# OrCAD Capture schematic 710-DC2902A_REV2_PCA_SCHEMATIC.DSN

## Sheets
1 PAGE2
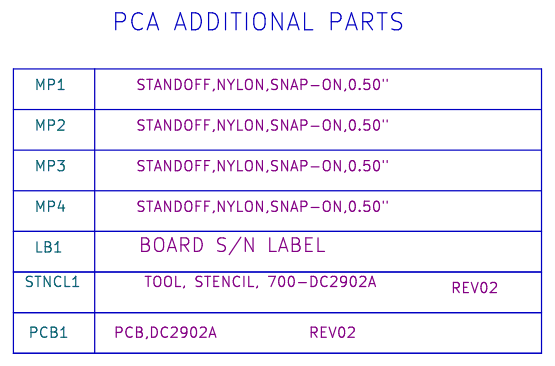
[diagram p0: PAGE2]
2 PAGE1: size C; note: ULTRA TINY 1.5A TEC uMODULE REGULATOR
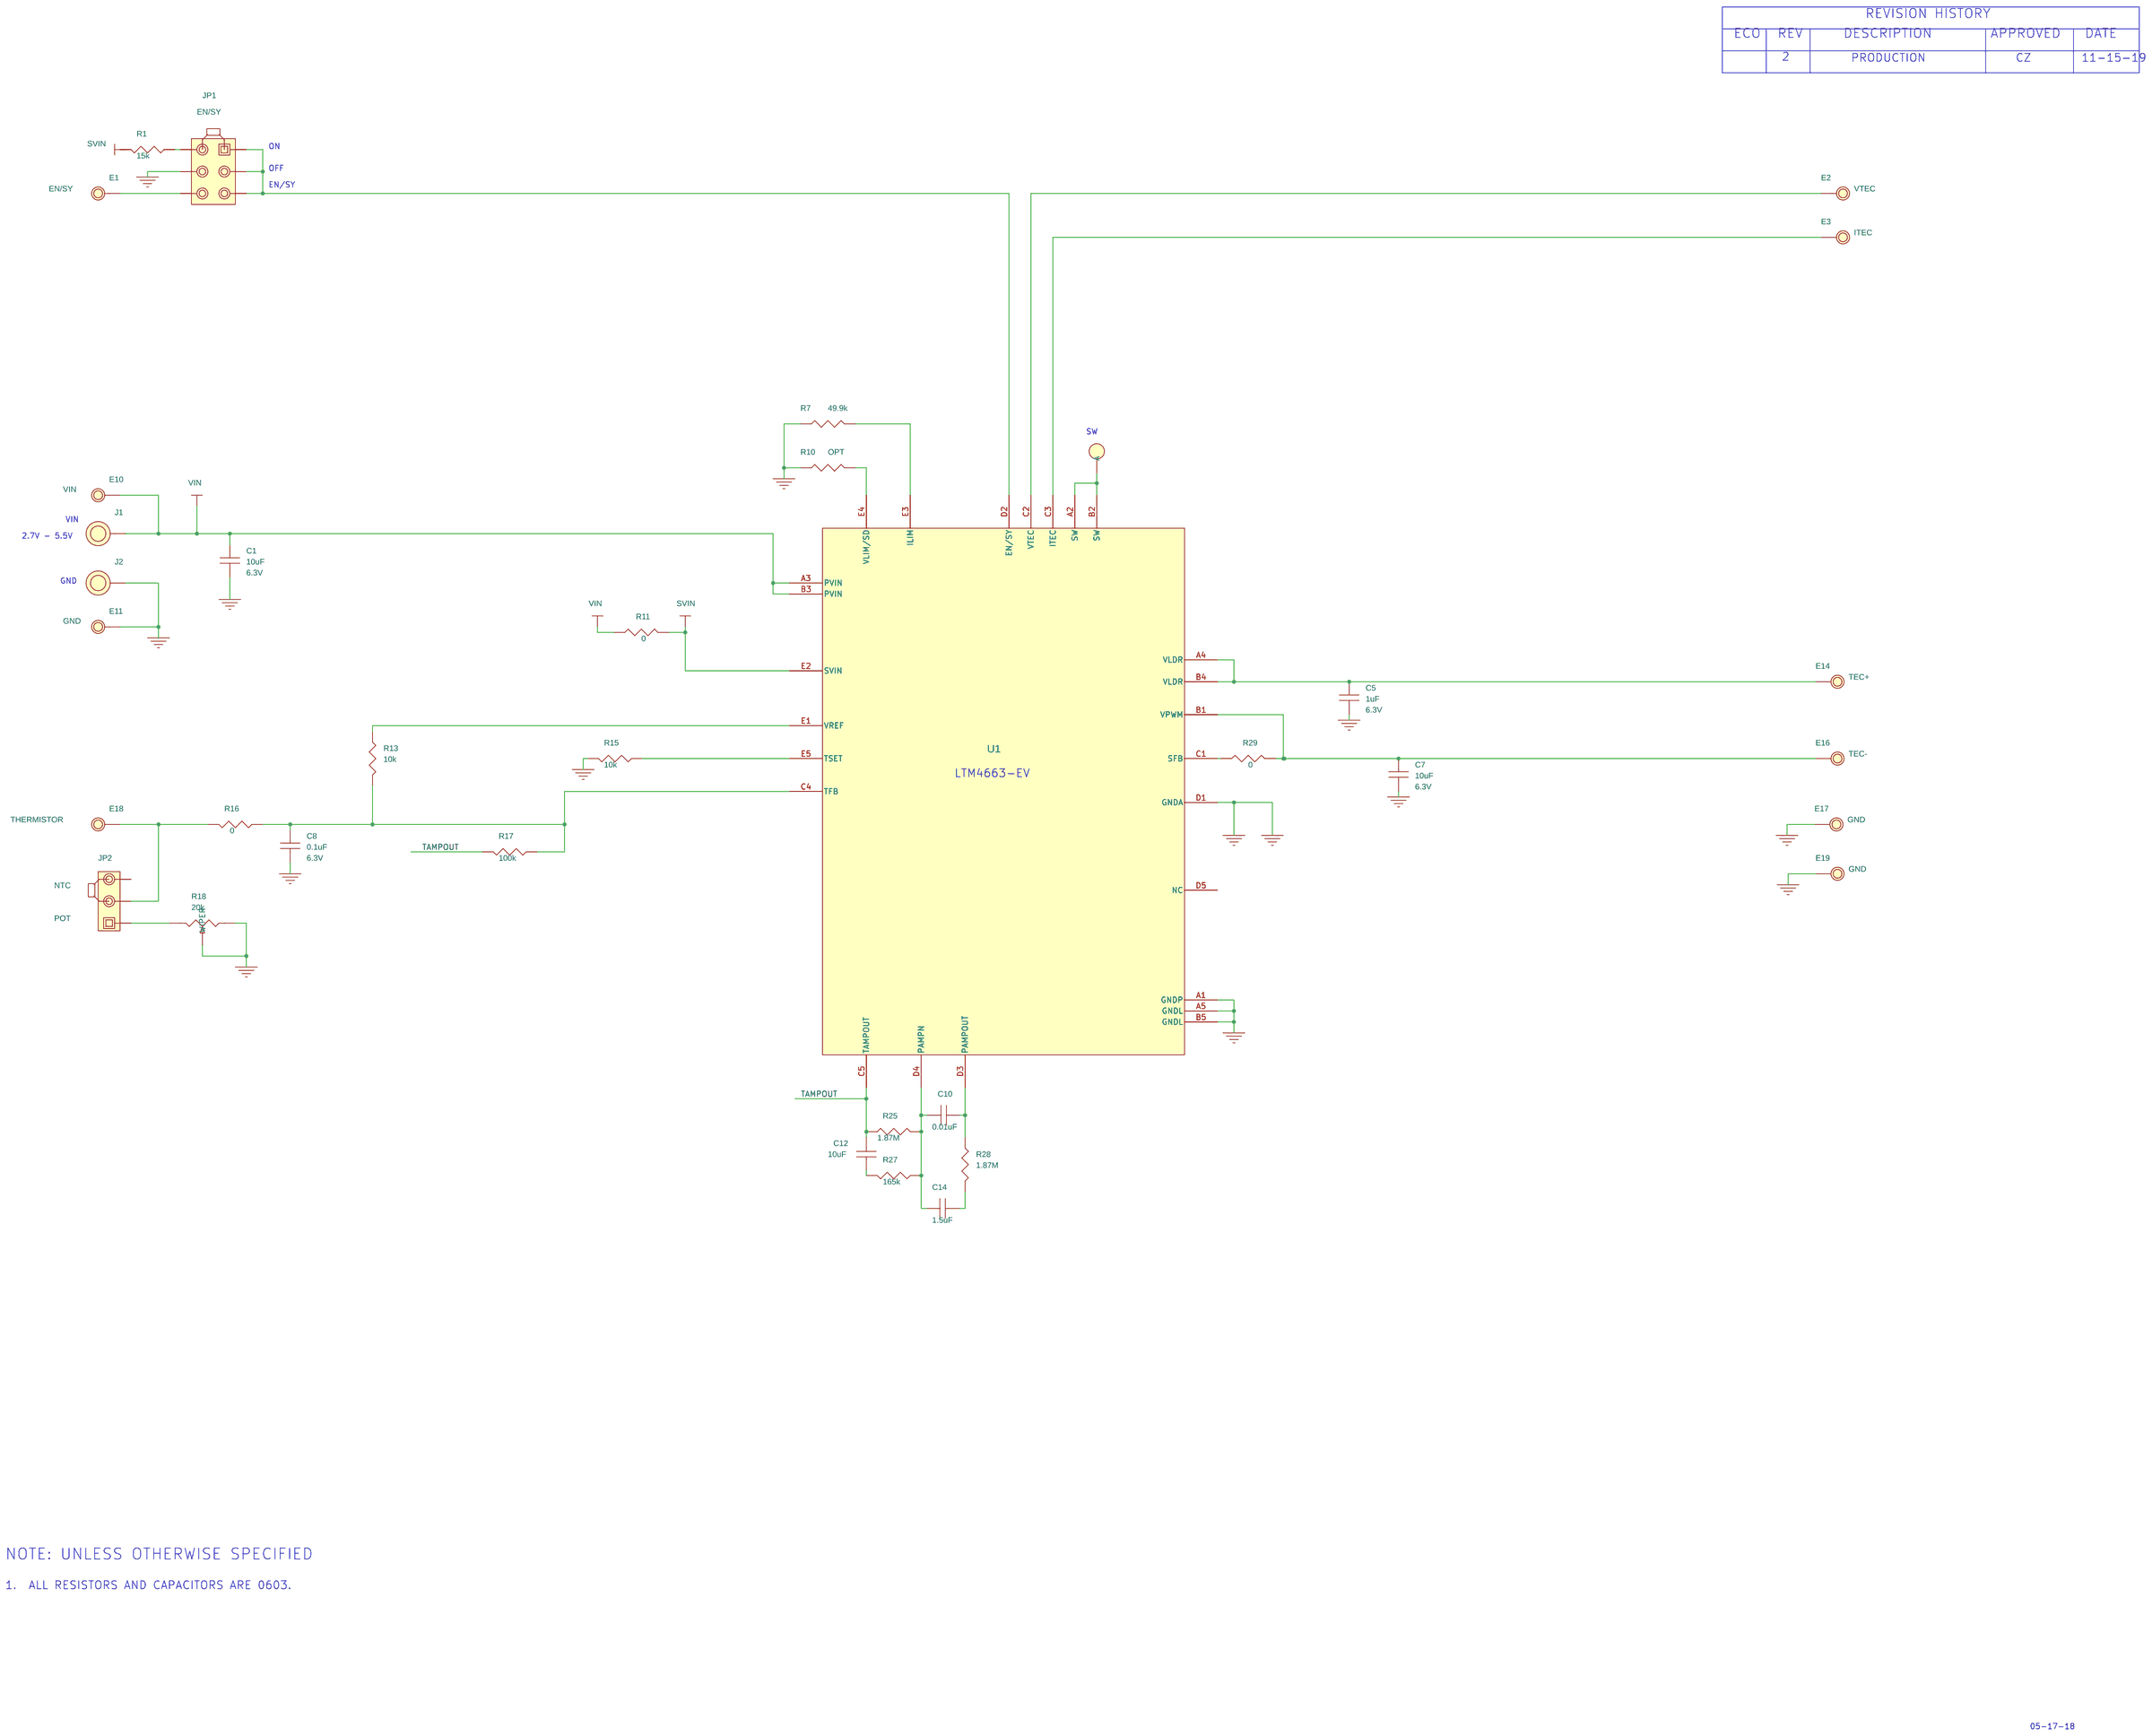
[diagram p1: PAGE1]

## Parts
sheet PAGE1
C1  10uF  [CC0603N]
C5  1uF  [CC0603N]
C7  10uF  [CC0603N]
C8  0.1uF  [CC0603N]
C10  0.01uF  [CC0603N]
C12  10uF  [CC0603N]
C14  1.5uF  [CC0603N]
E1  TEST POINT  [MILLMAX2308]
E2  TEST POINT  [MILLMAX2308]
E3  TEST POINT  [MILLMAX2308]
E10  TEST POINT  [MILLMAX2308]
E11  TEST POINT  [MILLMAX2308]
E14  TEST POINT  [MILLMAX2308]
E16  TEST POINT  [MILLMAX2308]
E17  TEST POINT  [MILLMAX2308]
E18  TEST POINT  [MILLMAX2308]
E19  TEST POINT  [MILLMAX2308]
J1  BANANA JACK  [KEY-575-4]
J2  BANANA JACK  [KEY-575-4]
JP1  HDR.  [HD2X3-079]
JP2  HDR.  [HD1X3-079]
R1  15k  [CR0603N]
R7  49.9k  [CR0603N]
R10  OPT  [CR0603N]
R11  0  [CR0603N]
R13  10k  [CR0603N]
R15  10k  [CR0603N]
R16  0  [CR0603N]
R17  100k  [CR0603N]
R18  20k  [BOURNS-3224W]
R25  1.87M  [CR0603N]
R27  165k  [CR0603N]
R28  1.87M  [CR0603N]
R29  0  [CR0603N]
TP1  TP  [PAD050-025]
U1  LTM4663-BGA  [LTC-BGA-25-1627]
XJP1  SHUNT
XJP2  SHUNT
sheet PAGE2
LB1  LABEL  [895-0154_REV01]
MP1  STANDOFF  [KEYSTONE_8829-8834]
MP2  STANDOFF  [KEYSTONE_8829-8834]
MP3  STANDOFF  [KEYSTONE_8829-8834]
MP4  STANDOFF  [KEYSTONE_8829-8834]
PCB1  PCB,DC2902A  [MECHANICAL_PART]
STNCL1  TOOL, STENCIL, 700-DC2902A

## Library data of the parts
C1 C7 C12 = CAP: CAP.,10uF,X5R,6.3V,10%,0603; CLASS: DISCRETE; Component: cap; Dielectric Type: X5R; FPLIST: CC0603N,CC0603L,CC0603M; Inventory Qty: 45256; Manufacturer: AVX; Manufacturer PN: 06036D106KAT2A; PART_NUMBER: 150-2243; Package Size: 0603; Rated Voltage: 6.3V; Tolerance: 10%
C5 = CAP: CAP.,1uF,X5R,6.3V,10%,0603; CLASS: DISCRETE; Component: cap; Dielectric Type: X5R; FPLIST: CC0603N,CC0603L,CC0603M; Inventory Qty: 2326; Manufacturer: AVX; Manufacturer PN: 06036D105KAT2A; PART_NUMBER: 150-2017; Package Size: 0603; Rated Voltage: 6.3V; Tolerance: 10%
C8 = CAP: CAP.,0.1uF,X7R,6.3V,10%,0603; CLASS: DISCRETE; Component: cap; Dielectric Type: X7R; FPLIST: CC0603N,CC0603L,CC0603M; Inventory Qty: 24974; Manufacturer: AVX; Manufacturer PN: 06036C104KAT2A; PART_NUMBER: 150-0680; Package Size: 0603; Package Type: SMD; Rated Voltage: 6.3V; Tolerance: 10%
C10 = CAP: CAP.,0.01uF,X5R,50V,10%,0603; CLASS: DISCRETE; Component: cap; Dielectric Type: X5R; FPLIST: CC0603N,CC0603L,CC0603M; Inventory Qty: 39974; Manufacturer: AVX; Manufacturer PN: 06035D103KAT2A; PART_NUMBER: 150-0049; Package Size: 0603; Rated Voltage: 50V; Tolerance: 10%
C14 = CAP: CAP.,1.5uF,X7R,10V,10%,0603; CLASS: DISCRETE; Dielectric Type: X7R; Inventory Qty: 980; Manufacturer: TDK; Manufacturer PN: C1608X7R1A155K080AC; PART_NUMBER: 150-0808; Package Size: 0603; Rated Voltage: 10V; Tolerance: 10%
E1 = TEST_POINT_.156_MILL-MAX_2308_A: TEST POINT,TURRET,0.064" MTG. HOLE,PCB 0.062" THK; CLASS: IO; Inventory Qty: 714348; Manufacturer: MILL-MAX; Manufacturer PN: 2308-2-00-80-00-00-07-0; PART_FIELD_01: EN/SY; PART_NUMBER: 260-0004
E2 = TEST_POINT_.156_MILL-MAX_2308_A: TEST POINT,TURRET,0.064" MTG. HOLE,PCB 0.062" THK; CLASS: IO; Inventory Qty: 714348; Manufacturer: MILL-MAX; Manufacturer PN: 2308-2-00-80-00-00-07-0; PART_FIELD_01: VTEC; PART_NUMBER: 260-0004
E3 = TEST_POINT_.156_MILL-MAX_2308_A: TEST POINT,TURRET,0.064" MTG. HOLE,PCB 0.062" THK; CLASS: IO; Inventory Qty: 714348; Manufacturer: MILL-MAX; Manufacturer PN: 2308-2-00-80-00-00-07-0; PART_FIELD_01: ITEC; PART_NUMBER: 260-0004
E10 = TEST_POINT_.156_MILL-MAX_2308_A: TEST POINT,TURRET,0.064" MTG. HOLE,PCB 0.062" THK; CLASS: IO; Inventory Qty: 714348; Manufacturer: MILL-MAX; Manufacturer PN: 2308-2-00-80-00-00-07-0; PART_FIELD_01: VIN; PART_NUMBER: 260-0004
E11 E17 E19 = TEST_POINT_.156_MILL-MAX_2308_A: TEST POINT,TURRET,0.064" MTG. HOLE,PCB 0.062" THK; CLASS: IO; Inventory Qty: 714348; Manufacturer: MILL-MAX; Manufacturer PN: 2308-2-00-80-00-00-07-0; PART_FIELD_01: GND; PART_NUMBER: 260-0004
E14 = TEST_POINT_.156_MILL-MAX_2308_A: TEST POINT,TURRET,0.064" MTG. HOLE,PCB 0.062" THK; CLASS: IO; Inventory Qty: 714348; Manufacturer: MILL-MAX; Manufacturer PN: 2308-2-00-80-00-00-07-0; PART_FIELD_01: TEC+; PART_NUMBER: 260-0004
E16 = TEST_POINT_.156_MILL-MAX_2308_A: TEST POINT,TURRET,0.064" MTG. HOLE,PCB 0.062" THK; CLASS: IO; Inventory Qty: 714348; Manufacturer: MILL-MAX; Manufacturer PN: 2308-2-00-80-00-00-07-0; PART_FIELD_01: TEC-; PART_NUMBER: 260-0004
E18 = TEST_POINT_.156_MILL-MAX_2308_A: TEST POINT,TURRET,0.064" MTG. HOLE,PCB 0.062" THK; CLASS: IO; Inventory Qty: 714348; Manufacturer: MILL-MAX; Manufacturer PN: 2308-2-00-80-00-00-07-0; PART_FIELD_01: THERMISTOR; PART_NUMBER: 260-0004
J1 J2 = BANANA_KEYSTONE-575-4_B: CONN.,BANANA JACK,FEMALE,THT,NON-INSULATED,SWAGE,0.218"; CLASS: IO; Inventory Qty: 182261; Manufacturer: KEYSTONE; Manufacturer PN: 575-4; PART_NUMBER: 250-0428
JP1 = HDR2X3_ALT1: CONN.,HDR.,MALE,2x3,2mm,VERT,ST,THT; 9th Part Field: EN/SY; CLASS: IO; Inventory Qty: 16324; Manufacturer: WURTH ELEKTRONIK; Manufacturer PN: 62000621121; PART_NUMBER: 250-0483
JP2 = HDR1X3_ALT1: CONN.,HDR.,MALE,1x3,2mm,VERT,STR,THT; 11th Part Field: NTC; 12th Part Field: XX; 9th Part Field: POT; CLASS: IO; Inventory Qty: 222902; Manufacturer: SULLINS CONNECTOR SOLUTIONS; Manufacturer PN: NRPN031PAEN-RC; PART_NUMBER: 250-0418
R1 = RES: RES.,15k OHMS,1%,1/10W,0603; CLASS: DISCRETE; FPLIST: CR0603N,CR0603L,CR0603M; Inventory Qty: 31932; Manufacturer: NIC; Manufacturer PN: NRC06F1502TRF; PART_NUMBER: 100-2757; Package Size: 0603; Rated Power: 1/10W; Temperature Coefficient: 100ppm/C; Tolerance: 1%
R7 = RES: RES.,49.9k OHMS,1%,1/10W,0603,AEC-Q200; CLASS: DISCRETE; FPLIST: CR0603N,CR0603L,CR0603M; Inventory Qty: 39980; Manufacturer: KOA SPEER; Manufacturer PN: RK73H1JTTD4992F; PART_NUMBER: 100-1555; Package Size: 0603; Rated Power: 1/10W; Temperature Coefficient: +/-100ppm; Tolerance: 1%
R10 = RES: RES., OPTION, 0603; CLASS: DISCRETE; FPLIST: CR0603N,CR0603L,CR0603M; PART_NUMBER: 100-2374; Package Size: 0603
R11 R16 R29 = RES: RES.,0 OHM,1/10W,0603,AEC-Q200; CLASS: DISCRETE; FPLIST: CR0603N,CR0603L,CR0603M; Inventory Qty: 617768; Manufacturer: VISHAY; Manufacturer PN: CRCW06030000Z0EA; PART_NUMBER: 100-0009; Package Size: 0603; Rated Power: 1/10W
R13 R15 = RES: RES.,10k OHMS,1%,1/10W,0603,AEC-Q200; CLASS: DISCRETE; FPLIST: CR0603N,CR0603L,CR0603M; Inventory Qty: 131562; Manufacturer: VISHAY; Manufacturer PN: CRCW060310K0FKEA; PART_NUMBER: 100-2012; Package Size: 0603; Rated Power: 1/10W; Temperature Coefficient: +/-100ppm/C; Tolerance: 1%
R17 = RES: RES.,100k OHMS,1%,1/10W,0603,AEC-Q200; CLASS: DISCRETE; FPLIST: CR0603N,CR0603L,CR0603M; Inventory Qty: 184726; Manufacturer: VISHAY; Manufacturer PN: CRCW0603100KFKEA; PART_NUMBER: 100-0343; Package Size: 0603; Rated Power: 1/10W; Temperature Coefficient: +/-100ppm; Tolerance: 1%
R18 = TRIMPOT: RES.,20K OHMS,10%,1/4W,SMD 4.8x3.9mm,12 TURN, TOP ADJUST, TRIMPOT; CLASS: DISCRETE; Inventory Qty: 974; Manufacturer: BOURNS; Manufacturer PN: 3224W-1-203E; PART_NUMBER: 103-0011; Package Size: SMD 4.8x3.9mm; Rated Power: 1/4W; Temperature Coefficient: +/- 100PPM; Tolerance: 10%
R25 R28 = RES: RES.,1.87M OHMS,1%,1/10W,0603; CLASS: DISCRETE; Inventory Qty: 24948; Manufacturer: VISHAY; Manufacturer PN: CRCW06031M87FKEA; PART_NUMBER: 100-1144; Package Size: 0603; Rated Power: 1/10W; Temperature Coefficient: +/-100PPM; Tolerance: 1%
R27 = RES: RES.,165k OHMS,1%,1/10W,0603,AEC-Q200; CLASS: DISCRETE; FPLIST: CR0603N,CR0603L,CR0603M; Inventory Qty: 19395; Manufacturer: PANASONIC; Manufacturer PN: ERJ3EKF1653V; PART_NUMBER: 100-0344; Package Size: 0603; Rated Power: 1/10W; Temperature Coefficient: 100ppm; Tolerance: 1%
TP1 = TP
U1 = LTM4663-BGA: IC,1.5A TEC uModule Regulator,LGA (3.5mmX4mmX1.3mm); CLASS: IC; Inventory Qty: 0; Manufacturer: ANALOG DEVICES; Manufacturer PN: LTM4663EV#PBF; PART_NUMBER: LTM4663EV#PBF; Package Size: BGA,25; Package Type: LGA (3.5mmX4mmX1.3mm)
XJP1 XJP2 = SHUNT_2MM: CONN.,SHUNT,FEMALE,2 POS,2mm; CLASS: IO; Inventory Qty: 72096; Manufacturer: Wurth Elektronik; Manufacturer PN: 60800213421; PART_NUMBER: 250-0485
LB1 = BLANK_LABEL: LABEL SPEC, DEMO BOARD SERIAL NUMBER; Inventory Qty: 0; Manufacturer: BRADY; Manufacturer PN: THT-96-717-10; PART_FIELD_01: BOARD S/N LABEL; PART_NUMBER: 895-0154
MP1-MP4 = BLANK_MECHANICAL_PART: STANDOFF,NYLON,SNAP-ON,0.50"; CLASS: DISCRETE; FPLIST: KEYSTONE_8829-8834,MTG-8831; Inventory Qty: 183560; Manufacturer: KEYSTONE; Manufacturer PN: 8833; PART_NUMBER: 763-0007
PCB1 = BLANK_PCB_PART: BOM Notes: REV02; CLASS: DISCRETE; Inventory Qty: 0; Manufacturer: PHASE 3; Manufacturer PN: 600-DC2902A; PART_NUMBER: 600-DC2902A
STNCL1 = BLANK_STENCIL_PART: BOM Notes: REV02; CLASS: DISCRETE; Inventory Qty: 0; Manufacturer: ANALOG DEVICES; Manufacturer PN: 830-DC2902A; PART_NUMBER: 830-DC2902A

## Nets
GND: C1.2 C5.2 C7.2 C8.2 E11.1 E17.1 E19.1 J2.1 JP1.4 R7.2 R10.2 R15.1 R18.1 R18.2(WIPER) U1.A1(GNDP) U1.A5(GNDL) U1.B5(GNDL) U1.D1(GNDA)
SVIN: R1.1 R11.1 U1.E2(SVIN)
VIN: C1.1 E10.1 J1.1 R11.2 U1.A3(PVIN) U1.B3(PVIN)
TAMPOUT: C12.2 R17.1 R25.1 U1.C5(TAMPOUT)
N5694593: C5.1 E14.1 U1.A4(VLDR) U1.B4(VLDR)
N5694829: C7.1 E16.1 R29.1 U1.B1(VPWM)
N5698457: C10.2 C14.1 R25.2 R27.2 U1.D4(PAMPN)
N5698478: C12.1 R27.1
N5698506: C10.1 R28.1 U1.D3(PAMPOUT)
N5699606: C14.2 R28.2
N5704318: R13.2 U1.E1(VREF)
N5704694: C8.1 R13.1 R16.2 R17.2 U1.C4(TFB)
N5704756: E18.1 JP2.2 R16.1
N5704817: JP2.1 R18.3
N5708826: R10.1 U1.E4(VLIM/SD)
N5708840: R7.1 U1.E3(ILIM)
N5714054: E2.1 U1.C2(VTEC)
N5714063: E3.1 U1.C3(ITEC)
N5714146: TP1.1(A) U1.A2(SW) U1.B2(SW)
N5719058: JP1.2 R1.2
N5719377: E1.1 JP1.6
N5719512: JP1.1 JP1.3 JP1.5 U1.D2(EN/SY)
N5737358: R29.2 U1.C1(SFB)
N5738313: R15.2 U1.E5(TSET)

Not connected (* = marked no-connect by the designer): JP2 3; U1 D5(NC)

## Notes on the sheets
sheet 1
- PCA ADDITIONAL PARTS
sheet 2
- REVISION HISTORY
- ECO
- REV
- DESCRIPTION
- APPROVED
- DATE
- 2
- PRODUCTION
- CZ
- 11-15-19
- ON
- OFF
- EN/SY
- SW
- VIN
- 2.7V - 5.5V
- GND
- LTM4663-EV
- NOTE: UNLESS OTHERWISE SPECIFIED
- 1.  ALL RESISTORS AND CAPACITORS ARE 0603.
- 05-17-18
